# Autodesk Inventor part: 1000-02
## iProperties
Created: 2012-08
Part Number: 1000-02
Document SubType Name: Modeling
Designer: Administrator
Density: 7.85 g/cm^3
Material: Steel
Mass: 8.01177 g
Surface Area: 12.5722 cm^2
Volume: 1.02061 cm^3
Author: Administrator
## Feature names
1. Base1
